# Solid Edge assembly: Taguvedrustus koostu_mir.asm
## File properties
Author: Türk
Template: Iso Assembly.asm
Last saved by: Türk
Revision: 8
Application: Solid Edge
Username: Türk
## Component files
Hoidja.tagu.par
Poldikoostu6.asm
si.par
Poldikoostu8.asm
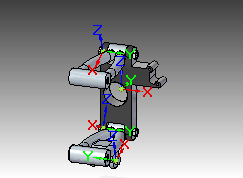
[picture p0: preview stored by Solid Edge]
